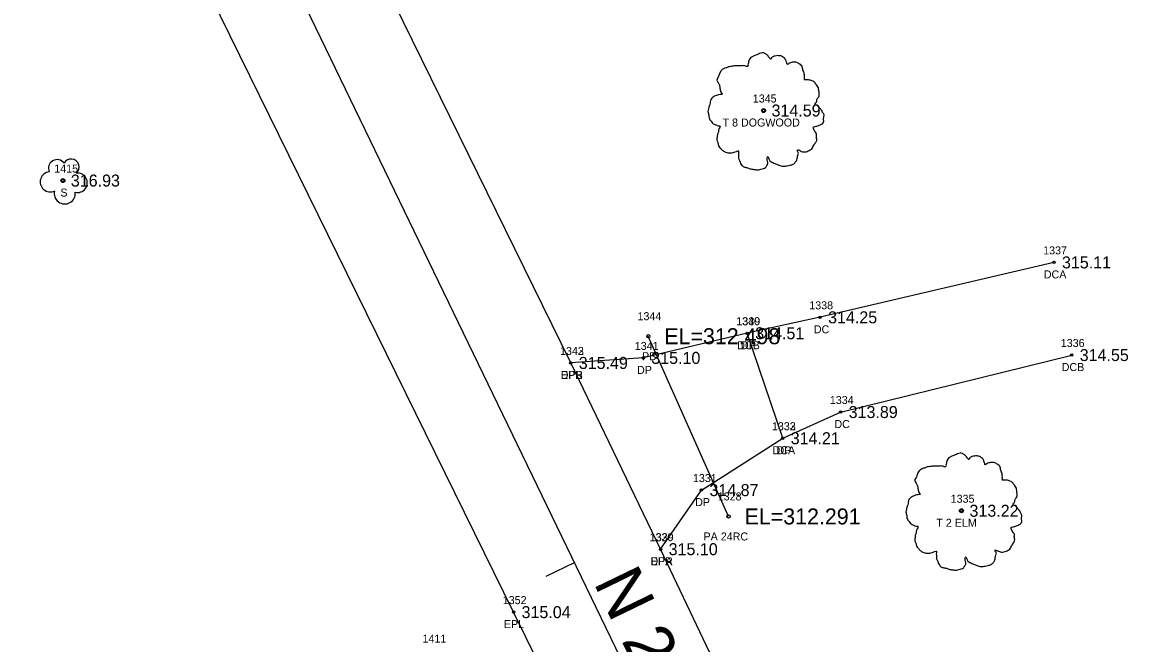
# Model space of a CAD drawing. Extents: x 1865045 to 1867370, y 910391 to 914218.
# Drawn here: x 1866074.6 to 1866214.8, y 911568.1 to 911645.7 of the extents above; entities that cross this region are included whole.
import ezdxf

# ---------------------------------------------------------------- set-up
doc = ezdxf.new("R2010")
doc.units = 0
for name, color, linetype in [('RD_EX_Conc', 7, 'Continuous'), ('RD_EX_Conc_txCode', 7, 'Continuous'), ('RD_EX_DR_Pipe', 7, 'Continuous'), ('RD_EX_DR_Pipe_txCode', 7, 'Continuous'), ('RD_EX_Driveway', 7, 'Continuous'), ('RD_EX_Driveway_txCode', 7, 'Continuous'), ('RD_EX_Road', 7, 'Continuous'), ('RD_EX_Road_txCode', 7, 'Continuous'), ('RD_EX_TX_Conc_ELEV', 7, 'Continuous'), ('RD_EX_TX_Driveway_ELEV', 7, 'Continuous'), ('RD_EX_TX_Road_ELEV', 7, 'Continuous'), ('RD_EX_TX_VEG_ELEV', 7, 'Continuous'), ('RD_EX_VEG', 7, 'Continuous'), ('RD_EX_VEG_txCode', 7, 'Continuous'), ('RD_HC_Cl', 7, 'Continuous'), ('RD_HC_Data', 7, 'Continuous'), ('RD_HC_Data_Tic', 7, 'Continuous'), ('RD_SMD_Locator', 7, 'Continuous'), ('RD_TX_Pipe_ElevEX', 7, 'Continuous')]:
    doc.layers.add(name, color=color, linetype=linetype)

msp = doc.modelspace()

# ---------------------------------------------------------------- linework, layer by layer
at = {"layer": 'RD_EX_Conc'}
for points in [[(1866203.47, 911615.73), (1866174.24, 911608.87), (1866165.13, 911606.88)], [(1866169.57, 911593.77), (1866176.81, 911597.04), (1866205.69, 911604.16)]]:
    msp.add_lwpolyline(points, dxfattribs=at)
at = {"layer": 'RD_EX_DR_Pipe'}
msp.add_line((1866162.8, 911584), (1866152.77, 911606.51), dxfattribs=at)
at = {"layer": 'RD_EX_Driveway'}
msp.add_lwpolyline([(1866154.31, 911579.91), (1866159.41, 911587.29), (1866169.57, 911593.77), (1866165.13, 911606.88), (1866152.14, 911603.8), (1866143.08, 911603.17)], dxfattribs=at)
at = {"layer": 'RD_EX_Road'}
for points in [[(1866367.09, 911115.22), (1866376.17, 911119.76), (1866330.4, 911213.7), (1866286.92, 911304.16), (1866242.4, 911396.3), (1866197.74, 911488.67), (1866154.31, 911579.91), (1866143.08, 911603.17), (1866108.16, 911674.25), (1866059.64, 911774.84), (1866048.38, 911798.67), (1866045.99, 911803.62)], [(1866367.09, 911115.22), (1866357.99, 911110.97), (1866313.12, 911203.44), (1866268.86, 911295.9), (1866224.24, 911388.66), (1866179.87, 911480.6), (1866149.84, 911543.41), (1866142.18, 911559.37), (1866135.93, 911572.05), (1866096.83, 911651.51), (1866089.65, 911665.46), (1866062.87, 911720.39), (1866042.14, 911765.69), (1866027.93, 911795.04)]]:
    msp.add_lwpolyline(points, dxfattribs=at)
at = {"layer": 'RD_EX_VEG'}
for centre, radius in [((1866167.17, 911634.7), 0.25), ((1866167.16, 911634.69), 0.0001), ((1866079.6, 911625.95), 0.25), ((1866191.91, 911584.71), 0.25), ((1866191.9, 911584.69), 0.0001)]:
    msp.add_circle(centre, radius, dxfattribs=at)
for centre, radius, start, end in [((1866078.88, 911627.49), 1.08, 34.9763, 204.756), ((1866080.64, 911627.65), 0.995, 308.7626, 152.0467), ((1866078.03, 911625.79), 1.26, 96.4518, 294.734), ((1866081.44, 911625.67), 1.22, 256.5667, 98.1046), ((1866079.84, 911624.35), 1.32, 166.8827, 5.7589)]:
    msp.add_arc(centre, radius, start, end, dxfattribs=at)
for points in [[(1866167.3, 911641.87), (1866167, 911641.9), (1866166.68, 911641.8), (1866166.43, 911641.7), (1866166.2, 911641.62), (1866165.98, 911641.52), (1866165.68, 911641.35), (1866165.45, 911641.15), (1866165.33, 911640.9), (1866165.28, 911640.67), (1866165.23, 911640.4), (1866165.23, 911640.22), (1866165.11, 911640.2), (1866164.96, 911640.22), (1866164.71, 911640.3), (1866164.46, 911640.3), (1866164.21, 911640.3), (1866163.86, 911640.27), (1866163.51, 911640.27), (1866163.23, 911640.22), (1866162.91, 911640.17), (1866162.53, 911640.05), (1866162.18, 911639.92), (1866161.88, 911639.67), (1866161.63, 911639.2), (1866161.51, 911638.85), (1866161.36, 911638.6), (1866161.51, 911638.15), (1866161.68, 911637.8), (1866161.71, 911637.6), (1866161.78, 911637.17), (1866161.88, 911636.95), (1866162.01, 911636.75), (1866161.93, 911636.72), (1866161.56, 911636.67), (1866161.26, 911636.57), (1866160.83, 911636.35), (1866160.61, 911636.12), (1866160.51, 911635.8), (1866160.48, 911635.45), (1866160.38, 911635.25), (1866160.31, 911634.97), (1866160.28, 911634.9), (1866160.23, 911634.57), (1866160.33, 911634.12), (1866160.36, 911633.77), (1866160.48, 911633.55), (1866160.63, 911633.38), (1866160.81, 911633.13), (1866161.21, 911632.9), (1866161.53, 911632.8), (1866161.73, 911632.78), (1866161.56, 911632.28), (1866161.51, 911631.93), (1866161.38, 911631.53), (1866161.38, 911631.45), (1866161.33, 911630.98), (1866161.48, 911630.65), (1866161.56, 911630.28), (1866161.73, 911630.05), (1866162.01, 911629.75), (1866162.33, 911629.53), (1866162.83, 911629.4), (1866163.23, 911629.43), (1866163.81, 911629.6), (1866164.06, 911629.68), (1866164.03, 911629.5), (1866164.06, 911629.13), (1866164.06, 911628.7), (1866164.21, 911628.38), (1866164.31, 911628.1), (1866164.46, 911627.85), (1866164.78, 911627.63), (1866165.18, 911627.55), (1866165.6, 911627.4), (1866166.05, 911627.33), (1866166.55, 911627.3), (1866167.15, 911627.45), (1866167.43, 911627.58), (1866167.53, 911627.75), (1866167.73, 911628.13), (1866167.68, 911628.35), (1866167.7, 911628.95), (1866167.8, 911628.78), (1866167.98, 911628.43), (1866168.48, 911628.13), (1866168.88, 911627.95), (1866169.35, 911627.8), (1866169.65, 911627.73), (1866170.13, 911627.8), (1866170.5, 911627.88), (1866170.88, 911628), (1866171.18, 911628.28), (1866171.35, 911628.55), (1866171.4, 911628.83), (1866171.48, 911629.2), (1866171.53, 911629.38)], [(1866171.53, 911629.38), (1866171.45, 911629.55), (1866171.4, 911629.8), (1866171.48, 911629.78), (1866171.65, 911629.73), (1866171.93, 911629.6), (1866172.15, 911629.53), (1866172.48, 911629.55), (1866172.75, 911629.65), (1866173.2, 911629.93), (1866173.48, 911630.4), (1866173.75, 911630.8), (1866173.83, 911631.13), (1866173.78, 911631.35), (1866173.75, 911631.85), (1866173.55, 911632.1), (1866173.5, 911632.23), (1866173.4, 911632.63), (1866173.48, 911632.68), (1866173.75, 911632.73), (1866174.13, 911632.85), (1866174.4, 911632.98), (1866174.63, 911633.15), (1866174.7, 911633.38), (1866174.68, 911633.77), (1866174.73, 911634.17), (1866174.65, 911634.32), (1866174.55, 911634.47), (1866174.48, 911634.67), (1866174.33, 911634.82), (1866174.23, 911634.97), (1866174.13, 911635.07), (1866174, 911635.22), (1866173.83, 911635.35), (1866173.68, 911635.4), (1866173.63, 911635.55), (1866173.78, 911635.75), (1866173.83, 911635.85), (1866173.85, 911636.07), (1866174.08, 911636.42), (1866174.13, 911636.82), (1866174.08, 911637.25), (1866174.03, 911637.52), (1866173.88, 911637.8), (1866173.68, 911638.05), (1866173.55, 911638.22), (1866173.38, 911638.35), (1866173.05, 911638.47), (1866172.8, 911638.52), (1866172.45, 911638.52), (1866172.25, 911638.57), (1866172.28, 911638.62), (1866172.28, 911638.77), (1866172.28, 911639.05), (1866172.2, 911639.5), (1866172.05, 911640), (1866172.05, 911640.02), (1866171.95, 911640.27), (1866171.73, 911640.47), (1866171.55, 911640.57), (1866171.35, 911640.7), (1866171.1, 911640.72), (1866170.8, 911640.72), (1866170.53, 911640.67), (1866170.33, 911640.57), (1866170.15, 911640.45), (1866170.08, 911640.6), (1866169.98, 911640.9), (1866169.93, 911641.05), (1866169.78, 911641.22), (1866169.55, 911641.42), (1866169.1, 911641.55), (1866168.48, 911641.47), (1866168.18, 911641.27), (1866168.03, 911641.1), (1866167.98, 911641.22), (1866167.78, 911641.42), (1866167.68, 911641.6), (1866167.5, 911641.72), (1866167.35, 911641.82), (1866167.25, 911641.87)], [(1866192.04, 911591.88), (1866191.74, 911591.9), (1866191.42, 911591.8), (1866191.17, 911591.7), (1866190.94, 911591.63), (1866190.72, 911591.53), (1866190.42, 911591.35), (1866190.19, 911591.15), (1866190.07, 911590.9), (1866190.02, 911590.68), (1866189.97, 911590.4), (1866189.97, 911590.23), (1866189.84, 911590.2), (1866189.69, 911590.23), (1866189.44, 911590.3), (1866189.19, 911590.3), (1866188.94, 911590.3), (1866188.59, 911590.28), (1866188.24, 911590.28), (1866187.97, 911590.23), (1866187.64, 911590.18), (1866187.27, 911590.05), (1866186.92, 911589.93), (1866186.62, 911589.68), (1866186.37, 911589.2), (1866186.25, 911588.85), (1866186.1, 911588.6), (1866186.25, 911588.15), (1866186.42, 911587.8), (1866186.45, 911587.6), (1866186.52, 911587.18), (1866186.62, 911586.95), (1866186.75, 911586.75), (1866186.67, 911586.73), (1866186.3, 911586.68), (1866186, 911586.58), (1866185.57, 911586.35), (1866185.35, 911586.13), (1866185.25, 911585.8), (1866185.22, 911585.45), (1866185.12, 911585.25), (1866185.05, 911584.98), (1866185.02, 911584.9), (1866184.97, 911584.58), (1866185.07, 911584.13), (1866185.1, 911583.78), (1866185.22, 911583.55), (1866185.37, 911583.38), (1866185.55, 911583.13), (1866185.95, 911582.9), (1866186.27, 911582.8), (1866186.47, 911582.78), (1866186.3, 911582.28), (1866186.25, 911581.93), (1866186.12, 911581.53), (1866186.12, 911581.46), (1866186.07, 911580.98), (1866186.22, 911580.66), (1866186.3, 911580.28), (1866186.47, 911580.06), (1866186.75, 911579.76), (1866187.07, 911579.53), (1866187.57, 911579.41), (1866187.97, 911579.43), (1866188.54, 911579.61), (1866188.79, 911579.68), (1866188.77, 911579.51), (1866188.79, 911579.13), (1866188.79, 911578.71), (1866188.94, 911578.38), (1866189.04, 911578.11), (1866189.19, 911577.86), (1866189.52, 911577.63), (1866189.92, 911577.56), (1866190.34, 911577.41), (1866190.79, 911577.33), (1866191.29, 911577.31), (1866191.89, 911577.46), (1866192.17, 911577.58), (1866192.27, 911577.76), (1866192.47, 911578.13), (1866192.42, 911578.36), (1866192.44, 911578.96), (1866192.54, 911578.78), (1866192.72, 911578.43), (1866193.22, 911578.13), (1866193.62, 911577.96), (1866194.09, 911577.81), (1866194.39, 911577.73), (1866194.87, 911577.81), (1866195.24, 911577.88), (1866195.62, 911578.01), (1866195.92, 911578.28), (1866196.09, 911578.56), (1866196.14, 911578.83), (1866196.22, 911579.21), (1866196.27, 911579.38)], [(1866196.27, 911579.38), (1866196.19, 911579.56), (1866196.14, 911579.81), (1866196.22, 911579.78), (1866196.39, 911579.73), (1866196.67, 911579.61), (1866196.89, 911579.53), (1866197.22, 911579.56), (1866197.49, 911579.66), (1866197.94, 911579.93), (1866198.22, 911580.41), (1866198.49, 911580.81), (1866198.57, 911581.13), (1866198.52, 911581.36), (1866198.49, 911581.86), (1866198.29, 911582.11), (1866198.24, 911582.23), (1866198.14, 911582.63), (1866198.22, 911582.68), (1866198.49, 911582.73), (1866198.86, 911582.85), (1866199.14, 911582.98), (1866199.36, 911583.15), (1866199.44, 911583.38), (1866199.41, 911583.78), (1866199.46, 911584.18), (1866199.39, 911584.33), (1866199.29, 911584.48), (1866199.21, 911584.68), (1866199.06, 911584.83), (1866198.96, 911584.98), (1866198.86, 911585.08), (1866198.74, 911585.23), (1866198.57, 911585.35), (1866198.42, 911585.4), (1866198.37, 911585.55), (1866198.52, 911585.75), (1866198.57, 911585.85), (1866198.59, 911586.08), (1866198.82, 911586.43), (1866198.86, 911586.83), (1866198.82, 911587.25), (1866198.77, 911587.53), (1866198.62, 911587.8), (1866198.42, 911588.05), (1866198.29, 911588.23), (1866198.12, 911588.35), (1866197.79, 911588.48), (1866197.54, 911588.53), (1866197.19, 911588.53), (1866196.99, 911588.58), (1866197.02, 911588.63), (1866197.02, 911588.78), (1866197.02, 911589.05), (1866196.94, 911589.5), (1866196.79, 911590), (1866196.79, 911590.03), (1866196.69, 911590.28), (1866196.47, 911590.48), (1866196.29, 911590.58), (1866196.09, 911590.7), (1866195.84, 911590.73), (1866195.54, 911590.73), (1866195.27, 911590.68), (1866195.07, 911590.58), (1866194.89, 911590.45), (1866194.82, 911590.6), (1866194.72, 911590.9), (1866194.67, 911591.05), (1866194.52, 911591.23), (1866194.29, 911591.43), (1866193.84, 911591.55), (1866193.22, 911591.48), (1866192.92, 911591.28), (1866192.77, 911591.1), (1866192.72, 911591.23), (1866192.52, 911591.43), (1866192.42, 911591.6), (1866192.24, 911591.73), (1866192.09, 911591.83), (1866191.99, 911591.88)]]:
    msp.add_spline(points, degree=3, dxfattribs=at)
at = {"layer": 'RD_HC_Cl'}
msp.add_line((1866280.52, 911295.32), (1866034.98, 911802.56), dxfattribs=at)
at = {"layer": 'RD_HC_Data_Tic'}
msp.add_line((1866143.57, 911578.24), (1866139.97, 911576.49), dxfattribs=at)
at = {"layer": 'RD_SMD_Locator'}
for centre, radius in [((1866167.17, 911634.7), 0.15), ((1866079.6, 911625.95), 0.15), ((1866203.47, 911615.73), 0.15), ((1866174.24, 911608.87), 0.15), ((1866165.13, 911606.88), 0.15), ((1866165.13, 911606.88), 0.15), ((1866152.77, 911606.51), 0.2), ((1866205.69, 911604.16), 0.15), ((1866143.08, 911603.17), 0.15), ((1866143.08, 911603.17), 0.15), ((1866152.14, 911603.8), 0.15), ((1866176.81, 911597.04), 0.15), ((1866169.57, 911593.77), 0.15), ((1866169.57, 911593.77), 0.15), ((1866159.41, 911587.29), 0.15), ((1866191.91, 911584.71), 0.15), ((1866162.8, 911584), 0.2), ((1866154.31, 911579.91), 0.15), ((1866154.31, 911579.91), 0.15), ((1866135.93, 911572.05), 0.15)]:
    msp.add_circle(centre, radius, dxfattribs=at)

# ---------------------------------------------------------------- texts
at = {"layer": 'RD_EX_Conc_txCode'}
for s, p in [('1337', (1866202.12, 911616.73)), ('DCA', (1866202.2, 911613.73)), ('1338', (1866172.89, 911609.87)), ('1339', (1866163.79, 911607.88)), ('DC', (1866173.46, 911606.87)), ('DCB', (1866163.88, 911604.88)), ('1336', (1866204.32, 911605.16)), ('DCB', (1866204.44, 911602.16)), ('1334', (1866175.46, 911598.04)), ('1333', (1866168.22, 911594.77)), ('DC', (1866176.03, 911595.04)), ('DCA', (1866168.3, 911591.77))]:
    msp.add_text(s, height=1, dxfattribs=at).set_placement(p)
at = {"layer": 'RD_EX_DR_Pipe_txCode'}
for s, p in [('1344', (1866151.42, 911608.51)), ('PB', (1866151.99, 911603.51)), ('1328', (1866161.45, 911586)), ('PA 24RC', (1866159.67, 911581))]:
    msp.add_text(s, height=1, dxfattribs=at).set_placement(p)
at = {"layer": 'RD_EX_Driveway_txCode'}
for s, p in [('1340', (1866163.75, 911607.88)), ('1341', (1866151.08, 911604.8)), ('DP', (1866164.35, 911604.88)), ('1342', (1866141.74, 911604.17)), ('DP', (1866151.36, 911601.8)), ('DPB', (1866141.83, 911601.17)), ('1332', (1866168.22, 911594.77)), ('DP', (1866168.79, 911591.77)), ('1331', (1866158.35, 911588.29)), ('DP', (1866158.63, 911585.29)), ('1330', (1866152.92, 911580.91)), ('DPA', (1866153.04, 911577.91))]:
    msp.add_text(s, height=1, dxfattribs=at).set_placement(p)
at = {"layer": 'RD_EX_Road_txCode'}
for s, p in [('1343', (1866141.74, 911604.17)), ('EPR', (1866141.85, 911601.17)), ('1329', (1866152.96, 911580.91)), ('EPR', (1866153.08, 911577.91)), ('1352', (1866134.58, 911573.05)), ('EPL', (1866134.72, 911570.05))]:
    msp.add_text(s, height=1, dxfattribs=at).set_placement(p)
at = {"layer": 'RD_EX_TX_Conc_ELEV'}
for s, p in [('315.11', (1866204.47, 911614.98)), ('314.25', (1866175.24, 911608.12)), ('314.51', (1866166.13, 911606.13)), ('314.55', (1866206.69, 911603.41)), ('313.89', (1866177.81, 911596.29)), ('314.21', (1866170.57, 911593.02))]:
    msp.add_text(s, height=1.5, dxfattribs=at).set_placement(p)
at = {"layer": 'RD_EX_TX_Driveway_ELEV'}
for s, p in [('314.51', (1866166.13, 911606.13)), ('315.10', (1866153.14, 911603.05)), ('315.49', (1866144.08, 911602.42)), ('314.21', (1866170.57, 911593.02)), ('314.87', (1866160.41, 911586.54)), ('315.10', (1866155.31, 911579.16))]:
    msp.add_text(s, height=1.5, dxfattribs=at).set_placement(p)
at = {"layer": 'RD_EX_TX_Road_ELEV'}
for s, p in [('315.49', (1866144.08, 911602.42)), ('315.10', (1866155.31, 911579.16)), ('315.04', (1866136.93, 911571.3))]:
    msp.add_text(s, height=1.5, dxfattribs=at).set_placement(p)
at = {"layer": 'RD_EX_TX_VEG_ELEV'}
for s, p in [('314.59', (1866168.17, 911633.95)), ('316.93', (1866080.6, 911625.2)), ('313.22', (1866192.91, 911583.96))]:
    msp.add_text(s, height=1.5, dxfattribs=at).set_placement(p)
at = {"layer": 'RD_EX_VEG_txCode'}
for s, p in [('1345', (1866165.83, 911635.7)), ('T 8 DOGWOOD', (1866162.05, 911632.7)), ('1415', (1866078.53, 911626.95)), ('S', (1866079.29, 911623.95)), ('1335', (1866190.56, 911585.71)), ('T 2 ELM', (1866188.77, 911582.71)), ('1411', (1866124.55, 911568.24))]:
    msp.add_text(s, height=1, dxfattribs=at).set_placement(p)
at = {"layer": 'RD_HC_Data'}
msp.add_text('N 25%%d 49\' 51" W', height=6, rotation=295.8309, dxfattribs=at).set_placement((1866145.87, 911575.76))
at = {"layer": 'RD_TX_Pipe_ElevEX'}
for s, p in [('EL=312.498', (1866154.77, 911605.51)), ('EL=312.291', (1866164.8, 911583))]:
    msp.add_text(s, height=2, dxfattribs=at).set_placement(p)

doc.saveas('drawing.dxf')
